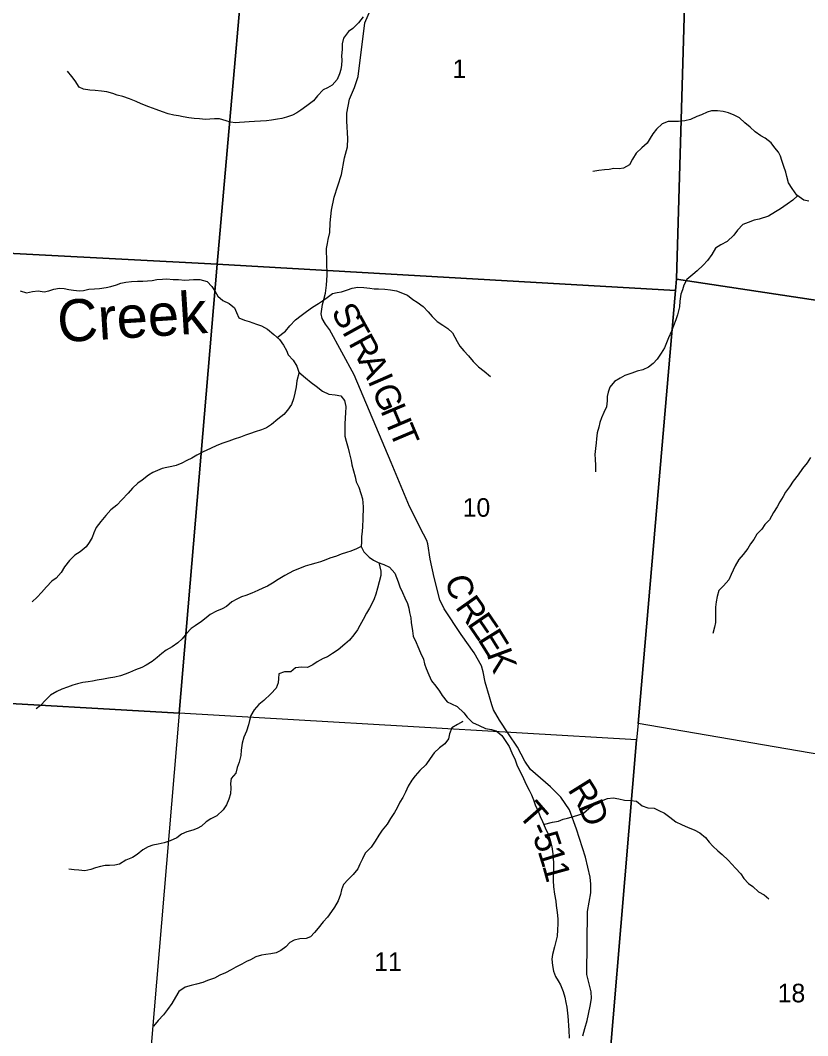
# Model space of a CAD drawing. Extents: x 0 to 34, y 0 to 22.
# Drawn here: x 26.568 to 28.342, y 14.481 to 16.768 of the extents above; entities that cross this region are included whole.
import ezdxf

# ---------------------------------------------------------------- set-up
doc = ezdxf.new("R2010")
doc.units = 0
for name, color, linetype in [('GM_X_Minor_River', 7, 'Continuous'), ('GM_X_Minor_River_Text', 7, 'Continuous'), ('GM_X_Section', 7, 'Continuous'), ('GM_X_Section_Text', 7, 'Continuous'), ('GM_X_Township_Road', 7, 'Continuous'), ('GM_X_Township_Road_Text', 7, 'Continuous')]:
    doc.layers.add(name, color=color, linetype=linetype)

msp = doc.modelspace()

# ---------------------------------------------------------------- linework, layer by layer
at = {"layer": 'GM_X_Minor_River'}
for points in [[(27.3405, 16.7762), (27.33, 16.7628), (27.3176, 16.7497), (27.3077, 16.7431), (27.2964, 16.7285), (27.2935, 16.7153), (27.2933, 16.7028), (27.2922, 16.6884), (27.2924, 16.6785), (27.2919, 16.6675), (27.2901, 16.6573), (27.2877, 16.6475), (27.2818, 16.6347), (27.2709, 16.6224), (27.2606, 16.6161), (27.2507, 16.6114), (27.2379, 16.598), (27.2286, 16.5871), (27.2141, 16.576), (27.2006, 16.5657), (27.191, 16.5598), (27.1815, 16.555), (27.1681, 16.5504), (27.1575, 16.5475), (27.1476, 16.5454), (27.1339, 16.543), (27.1226, 16.5421), (27.1093, 16.5412), (27.096, 16.5403), (27.0835, 16.5398), (27.0737, 16.5389), (27.0623, 16.5379), (27.0528, 16.5374), (27.0419, 16.5387), (27.0317, 16.5415), (27.0171, 16.5464), (27.0057, 16.5466), (26.9955, 16.5456), (26.9856, 16.5451), (26.972, 16.5465), (26.9599, 16.5475), (26.9482, 16.5488), (26.9354, 16.5509), (26.9245, 16.553), (26.9143, 16.5544), (26.9015, 16.5577), (26.8883, 16.5625), (26.874, 16.5677), (26.8575, 16.5733), (26.8402, 16.5804), (26.8293, 16.5852), (26.8143, 16.5915), (26.7989, 16.5964), (26.7868, 16.6), (26.7767, 16.6036), (26.7635, 16.6069), (26.7514, 16.609), (26.7371, 16.6101), (26.725, 16.6111), (26.711, 16.6132), (26.7009, 16.618), (26.692, 16.6318), (26.6847, 16.6414), (26.6747, 16.6537)], [(28.3447, 16.3609), (28.333, 16.363), (28.3173, 16.3747), (28.307, 16.3893), (28.2989, 16.4024), (28.2954, 16.4168), (28.2925, 16.4264), (28.2886, 16.4393), (28.2839, 16.4523), (28.2807, 16.4619), (28.276, 16.4714), (28.2682, 16.4811), (28.2601, 16.4926), (28.2463, 16.5027), (28.2366, 16.5082), (28.2235, 16.5172), (28.2123, 16.5273), (28.2004, 16.5377), (28.1881, 16.549), (28.1761, 16.5549), (28.1633, 16.5597), (28.1513, 16.5626), (28.1385, 16.5647), (28.1256, 16.5642), (28.1157, 16.5617), (28.1031, 16.5551), (28.092, 16.5515), (28.0779, 16.545), (28.0654, 16.5418), (28.0513, 16.5402), (28.0279, 16.5406), (28.0145, 16.5352), (28.0018, 16.5229), (27.9933, 16.5124), (27.9874, 16.5027), (27.9808, 16.4918), (27.9681, 16.4807), (27.9557, 16.4688), (27.9472, 16.4553), (27.9405, 16.4429), (27.9271, 16.4355), (27.9172, 16.4338), (27.9051, 16.4341), (27.8949, 16.4323), (27.8846, 16.4314), (27.8717, 16.4301), (27.8584, 16.4277)], [(28.3193, 16.3732), (28.3084, 16.3631), (28.2961, 16.3542), (28.2808, 16.3439), (28.2696, 16.3365), (28.2539, 16.327), (28.2326, 16.3205), (28.2212, 16.3177), (28.2079, 16.3127), (28.1961, 16.3083), (28.1837, 16.2953), (28.1755, 16.2844), (28.1605, 16.2699), (28.1467, 16.2622), (28.1341, 16.2549), (28.1259, 16.241), (28.1162, 16.2275), (28.1069, 16.2163), (28.093, 16.2041), (28.0834, 16.1959), (28.0696, 16.184), (28.0629, 16.1716), (28.0601, 16.1614), (28.0565, 16.1516), (28.0539, 16.1354), (28.0529, 16.1229), (28.0488, 16.1051), (28.0448, 16.0938), (28.0396, 16.0799), (28.0356, 16.0682), (28.0285, 16.0532), (28.0241, 16.0419), (28.0194, 16.0306), (28.0119, 16.0182), (28.003, 16.0051), (27.9941, 15.9954), (27.9837, 15.9865), (27.9707, 15.9807), (27.9578, 15.9779), (27.946, 15.9732), (27.9304, 15.9678), (27.9193, 15.9623), (27.907, 15.9549), (27.8962, 15.9419), (27.8922, 15.9302), (27.8905, 15.9204), (27.8903, 15.9109), (27.8885, 15.8976), (27.883, 15.8848), (27.8775, 15.8724), (27.8739, 15.8619), (27.8714, 15.8517), (27.8681, 15.8388), (27.866, 15.8256), (27.8654, 15.8161), (27.8637, 15.8033), (27.8623, 15.79), (27.8632, 15.7798), (27.8637, 15.765), (27.8638, 15.7513)], [(26.5681, 16.1592), (26.5823, 16.1544), (26.5956, 16.1572), (26.6089, 16.1588), (26.6221, 16.1567), (26.6328, 16.1591), (26.6442, 16.1627), (26.6563, 16.1648), (26.6669, 16.1642), (26.6775, 16.1621), (26.688, 16.1604), (26.7013, 16.1586), (26.7107, 16.1596), (26.7229, 16.1624), (26.7358, 16.1636), (26.7468, 16.1642), (26.7616, 16.1666), (26.7722, 16.1686), (26.7852, 16.1726), (26.7951, 16.1758), (26.8061, 16.1782), (26.8186, 16.1799), (26.8323, 16.1808), (26.844, 16.1809), (26.8546, 16.1811), (26.8652, 16.1821), (26.8762, 16.1845), (26.8887, 16.1854), (26.8986, 16.1856), (26.9126, 16.1846), (26.9243, 16.184), (26.939, 16.1829), (26.9489, 16.1835), (26.9587, 16.1845), (26.9731, 16.1846), (26.9893, 16.1801), (26.9997, 16.1689), (27.0074, 16.1574), (27.0133, 16.1466), (27.0245, 16.137), (27.0387, 16.1306), (27.0506, 16.1205), (27.055, 16.1102), (27.0604, 16.098), (27.0732, 16.0928), (27.0841, 16.0896), (27.1007, 16.0839), (27.1116, 16.0803), (27.125, 16.0721), (27.1392, 16.0608), (27.1519, 16.0492), (27.1614, 16.0361), (27.1677, 16.0243)], [(27.147, 16.0537), (27.1658, 16.0679), (27.1755, 16.0802), (27.1886, 16.0933), (27.2013, 16.1029), (27.2132, 16.1122), (27.2267, 16.1221), (27.2397, 16.1302), (27.2493, 16.1365), (27.2596, 16.1435), (27.2719, 16.1528), (27.2822, 16.1552), (27.292, 16.1566), (27.305, 16.1609), (27.3157, 16.1648), (27.3286, 16.1669), (27.3418, 16.1663), (27.3554, 16.1645), (27.3656, 16.1635), (27.3754, 16.1637), (27.3894, 16.1623), (27.4026, 16.1613), (27.4155, 16.1592), (27.4402, 16.1488), (27.4522, 16.1395), (27.4623, 16.1336), (27.4757, 16.1239), (27.4872, 16.1112), (27.4961, 16.1011), (27.5076, 16.0899), (27.5203, 16.0813), (27.5316, 16.0743), (27.542, 16.0642), (27.5471, 16.0543), (27.5526, 16.0447), (27.5584, 16.034), (27.5673, 16.0239), (27.5781, 16.0124), (27.5884, 15.9996), (27.6007, 15.9873), (27.6134, 15.9775), (27.6275, 15.9659)], [(27.1677, 16.0243), (27.1716, 16.0143), (27.1828, 16.0027), (27.1916, 15.9893), (27.1959, 15.9759), (27.2108, 15.9628), (27.2238, 15.9526), (27.2346, 15.9437), (27.2492, 15.9324), (27.2631, 15.9261), (27.2774, 15.9247), (27.2902, 15.9222), (27.2987, 15.9114), (27.3015, 15.8981), (27.3009, 15.8833), (27.3003, 15.8731), (27.2992, 15.8575), (27.2993, 15.8431), (27.2995, 15.831), (27.3023, 15.8203), (27.3069, 15.8043), (27.309, 15.7948), (27.3136, 15.7765), (27.3153, 15.767), (27.3188, 15.7529), (27.3227, 15.7395), (27.3252, 15.7285), (27.3306, 15.7166), (27.3357, 15.7025), (27.3388, 15.6903), (27.3404, 15.672), (27.3399, 15.644), (27.3392, 15.6277), (27.3382, 15.6167), (27.3372, 15.605), (27.3366, 15.5928), (27.3364, 15.5826), (27.3423, 15.5711), (27.3541, 15.5587), (27.3639, 15.5517), (27.3747, 15.547), (27.3871, 15.5422), (27.4003, 15.5359), (27.4121, 15.5224), (27.4193, 15.5033), (27.4233, 15.4918), (27.4291, 15.4788), (27.4349, 15.4673), (27.4404, 15.4547), (27.4436, 15.444), (27.4453, 15.4341), (27.4477, 15.4223), (27.449, 15.4117), (27.4521, 15.3927), (27.4533, 15.3805), (27.4603, 15.3667), (27.4639, 15.3572), (27.4697, 15.343), (27.4766, 15.3288), (27.479, 15.3186), (27.4826, 15.3082), (27.4888, 15.2933), (27.4946, 15.2803), (27.5042, 15.268), (27.5127, 15.2565), (27.5186, 15.2469), (27.53, 15.233), (27.5398, 15.2279), (27.5525, 15.222), (27.5678, 15.208), (27.5752, 15.1984), (27.5867, 15.1864), (27.6021, 15.1793), (27.6159, 15.173), (27.6299, 15.1701), (27.6404, 15.1672), (27.6531, 15.1567), (27.6609, 15.146), (27.6693, 15.1318), (27.6758, 15.118), (27.6827, 15.1019), (27.6874, 15.0889), (27.6962, 15.0728), (27.702, 15.0598), (27.7082, 15.0468), (27.7144, 15.0334), (27.7198, 15.0235), (27.7242, 15.0116), (27.7285, 15.0009), (27.735, 14.9864), (27.7397, 14.9742), (27.7444, 14.9631), (27.7506, 14.9485), (27.7571, 14.9344), (27.7618, 14.921), (27.7657, 14.9058), (27.768, 14.8902), (27.7696, 14.87), (27.7697, 14.856), (27.769, 14.8431), (27.7688, 14.8302)], [(27.1962, 15.9756), (27.191, 15.9563), (27.1899, 15.9423), (27.1867, 15.9283), (27.1838, 15.9158), (27.179, 15.903), (27.1704, 15.8899), (27.1619, 15.8802), (27.1481, 15.8695), (27.1342, 15.858), (27.1231, 15.8502), (27.1113, 15.8459), (27.0976, 15.8409), (27.0869, 15.8373), (27.0759, 15.8333), (27.064, 15.829), (27.0503, 15.8243), (27.0381, 15.8204), (27.0244, 15.8153), (27.0111, 15.8106), (26.9966, 15.8037), (26.9802, 15.7964), (26.9656, 15.7883), (26.9549, 15.7821), (26.9434, 15.7762), (26.9324, 15.7708), (26.9194, 15.7649), (26.9095, 15.7632), (26.8981, 15.7604), (26.8879, 15.7583), (26.8775, 15.754), (26.8669, 15.7492), (26.8569, 15.7434), (26.8427, 15.7322), (26.8327, 15.7256), (26.8212, 15.7141), (26.8111, 15.7033), (26.7968, 15.6876), (26.7856, 15.676), (26.7725, 15.6653), (26.761, 15.6526), (26.7497, 15.6392), (26.7389, 15.6253), (26.7341, 15.6137), (26.7301, 15.6027), (26.7231, 15.5915), (26.7165, 15.5818), (26.703, 15.571), (26.6908, 15.5629), (26.6792, 15.551), (26.6679, 15.5368), (26.6605, 15.524), (26.6493, 15.5113), (26.6397, 15.5047), (26.6273, 15.492), (26.6157, 15.479), (26.6065, 15.4689), (26.5953, 15.4581)], [(28.3485, 15.7835), (28.3407, 15.7712), (28.3306, 15.7588), (28.3205, 15.7442), (28.3093, 15.73), (28.3011, 15.7173), (28.2921, 15.7053), (28.2867, 15.6955), (28.2792, 15.6836), (28.273, 15.6723), (28.2648, 15.6595), (28.2558, 15.643), (28.2457, 15.6326), (28.2391, 15.6221), (28.2275, 15.6109), (28.2209, 15.5985), (28.2131, 15.5888), (28.2072, 15.5783), (28.1967, 15.5645), (28.1871, 15.5537), (28.1789, 15.5394), (28.1738, 15.5296), (28.1694, 15.5199), (28.1643, 15.5078), (28.1527, 15.4944), (28.1422, 15.4836), (28.1382, 15.4704), (28.1361, 15.4579), (28.1343, 15.4458), (28.1341, 15.4356), (28.1346, 15.4223), (28.1341, 15.4113), (28.1323, 15.4007), (28.1287, 15.3871)], [(27.3364, 15.5826), (27.3254, 15.5775), (27.3128, 15.572), (27.3032, 15.5692), (27.2914, 15.5652), (27.2804, 15.5613), (27.2659, 15.5562), (27.2564, 15.5526), (27.2449, 15.5479), (27.2343, 15.5451), (27.2206, 15.5415), (27.2103, 15.5383), (27.1974, 15.5332), (27.1836, 15.5278), (27.1741, 15.5227), (27.1641, 15.5172), (27.1492, 15.5087), (27.1362, 15.5003), (27.1254, 15.4933), (27.1148, 15.4889), (27.1033, 15.4838), (27.0899, 15.4776), (27.0766, 15.4726), (27.0663, 15.469), (27.056, 15.4642), (27.0449, 15.458), (27.0326, 15.4472), (27.0227, 15.4421), (27.0101, 15.4374), (26.9963, 15.4297), (26.9867, 15.4219), (26.9767, 15.4137), (26.9625, 15.4042), (26.9529, 15.3979), (26.9425, 15.3867), (26.9328, 15.3744), (26.9228, 15.3658), (26.9101, 15.3566), (26.8971, 15.3489), (26.8868, 15.3419), (26.8768, 15.3326), (26.8656, 15.324), (26.8522, 15.3156), (26.8423, 15.3101), (26.8278, 15.305), (26.8144, 15.2985), (26.8045, 15.2949), (26.7939, 15.2916), (26.7809, 15.2881), (26.7673, 15.2861), (26.7555, 15.2836), (26.7414, 15.2816), (26.7308, 15.2796), (26.7213, 15.2782), (26.7095, 15.2762), (26.697, 15.273), (26.6864, 15.2705), (26.6745, 15.2658), (26.662, 15.2611), (26.6509, 15.2564), (26.6367, 15.2479), (26.6256, 15.2375), (26.614, 15.2245), (26.6043, 15.2167)], [(27.376, 15.5465), (27.3808, 15.5271), (27.3806, 15.5173), (27.3766, 15.5033), (27.3729, 15.489), (27.3692, 15.475), (27.3652, 15.4648), (27.3601, 15.4536), (27.355, 15.4438), (27.3484, 15.4325), (27.3409, 15.4186), (27.3331, 15.4048), (27.328, 15.395), (27.3198, 15.3838), (27.3097, 15.3718), (27.2997, 15.3625), (27.2847, 15.3503), (27.2713, 15.3414), (27.2606, 15.3344), (27.2503, 15.3301), (27.2373, 15.3227), (27.2273, 15.3161), (27.2155, 15.3102), (27.2018, 15.3105), (27.1882, 15.3092), (27.1774, 15.3003), (27.1638, 15.3002), (27.1509, 15.2959), (27.1499, 15.2853), (27.1493, 15.2758), (27.1449, 15.2634), (27.1326, 15.2507), (27.1172, 15.2355), (27.1056, 15.2266), (27.0952, 15.2147), (27.0878, 15.2019), (27.0845, 15.191), (27.0821, 15.1808), (27.078, 15.1668), (27.0721, 15.1533), (27.0684, 15.1397), (27.0658, 15.1238), (27.0652, 15.1117), (27.0612, 15.0966), (27.0572, 15.0849), (27.0535, 15.0724), (27.0434, 15.0601), (27.0417, 15.0491), (27.0427, 15.0393), (27.0417, 15.0256), (27.0384, 15.0136), (27.0329, 15.0008), (27.0251, 14.9891), (27.0112, 14.9761), (26.9974, 14.9688), (26.9867, 14.9622), (26.9763, 14.9529), (26.9667, 14.9474), (26.9568, 14.9434), (26.9432, 14.9402), (26.9313, 14.9344), (26.9206, 14.9266), (26.906, 14.9197), (26.8923, 14.9154), (26.879, 14.9122), (26.8665, 14.9098), (26.8562, 14.9058), (26.8447, 14.8992), (26.8313, 14.8885), (26.8213, 14.8822), (26.8064, 14.8757), (26.7919, 14.8672), (26.7812, 14.8644), (26.7695, 14.8642), (26.7593, 14.8641), (26.749, 14.862), (26.7376, 14.8588), (26.7273, 14.8548), (26.7136, 14.852), (26.7, 14.8538), (26.6898, 14.8544), (26.6778, 14.8561)], [(27.5644, 15.1876), (27.5651, 15.1883), (27.5529, 15.1818), (27.5407, 15.1744), (27.5355, 15.1608), (27.5326, 15.1495), (27.5244, 15.1379), (27.5126, 15.1294), (27.5006, 15.1175), (27.4917, 15.1051), (27.4815, 15.0909), (27.4681, 15.0779), (27.458, 15.066), (27.4506, 15.0559), (27.4424, 15.0431), (27.4357, 15.0296), (27.4298, 15.0172), (27.4236, 15.0067), (27.4169, 14.9939), (27.411, 14.9834), (27.402, 14.9699), (27.3946, 14.9571), (27.3838, 14.9433), (27.3756, 14.9321), (27.3678, 14.9186), (27.3584, 14.9055), (27.3449, 14.8921), (27.339, 14.8793), (27.3331, 14.8669), (27.3284, 14.8567), (27.3179, 14.844), (27.3071, 14.8321), (27.2963, 14.8209), (27.2919, 14.8089), (27.2894, 14.7987), (27.2846, 14.7847), (27.276, 14.7701), (27.2694, 14.76), (27.2604, 14.7473), (27.2508, 14.7368), (27.2396, 14.723), (27.2314, 14.7133), (27.2218, 14.7029), (27.2119, 14.6993), (27.1982, 14.6984), (27.1849, 14.696), (27.1754, 14.6905), (27.1668, 14.6808), (27.1549, 14.6723), (27.145, 14.6675), (27.1329, 14.6647), (27.1215, 14.6634), (27.1116, 14.6617), (27.099, 14.6581), (27.0872, 14.6512), (27.0776, 14.6475), (27.0673, 14.642), (27.054, 14.6351), (27.0436, 14.6292), (27.0302, 14.6223), (27.0177, 14.6172), (27.0054, 14.6102), (26.9902, 14.6048), (26.9795, 14.6005), (26.9654, 14.5969), (26.9532, 14.5937), (26.9396, 14.5898), (26.9257, 14.5799), (26.9179, 14.5671), (26.9097, 14.5528), (26.8996, 14.5398), (26.8911, 14.5274), (26.8791, 14.5147), (26.8686, 14.5017)], [(27.7472, 14.9565), (27.7671, 14.9615), (27.7804, 14.9639), (27.7911, 14.9683), (27.8006, 14.9707), (27.8143, 14.9743), (27.8265, 14.9782), (27.8368, 14.9822), (27.8491, 14.9922), (27.8621, 15.0014), (27.8812, 15.0109), (27.8908, 15.0149), (27.9037, 15.0166), (27.9169, 15.0141), (27.9297, 15.0115), (27.9437, 15.0101), (27.9561, 15.0088), (27.9688, 14.9987), (27.9823, 14.9942), (27.9959, 14.9929), (28.0064, 14.9881), (28.0192, 14.9822), (28.0315, 14.9732), (28.0449, 14.9623), (28.0577, 14.956), (28.0731, 14.9497), (28.0862, 14.9445), (28.0994, 14.9374), (28.1116, 14.9273), (28.1198, 14.9169), (28.1283, 14.9073), (28.1398, 14.8972), (28.1495, 14.8887), (28.1629, 14.8763), (28.1792, 14.8582), (28.1915, 14.845), (28.1985, 14.835), (28.2088, 14.8235), (28.2186, 14.8164), (28.2316, 14.8048), (28.2443, 14.7978), (28.2548, 14.7892)], [(27.7688, 14.8302), (27.7693, 14.8158), (27.772, 14.7991), (27.7747, 14.7835), (27.7757, 14.7736), (27.7777, 14.7584), (27.7789, 14.7439), (27.7791, 14.7329), (27.7788, 14.7189), (27.7774, 14.7049), (27.7749, 14.6928), (27.772, 14.6811), (27.7668, 14.6634), (27.7655, 14.6532), (27.7671, 14.6387), (27.7695, 14.6258), (27.7738, 14.6139), (27.7797, 14.6043), (27.7852, 14.5948), (27.7913, 14.5802), (27.7952, 14.5676), (27.7973, 14.5555), (27.7994, 14.5448), (27.802, 14.5246), (27.8026, 14.5144), (27.8031, 14.5026), (27.8037, 14.4928), (27.8049, 14.4749)]]:
    msp.add_lwpolyline(points, dxfattribs=at)
at = {"layer": 'GM_X_Section'}
for points in [[(26.2538, 17.2713), (27.0604, 17.2208), (27.0998, 17.2184), (27.0114, 16.2186), (25.9802, 16.2732), (26.0152, 16.9679), (26.1318, 17.0242)], [(27.0998, 17.2184), (28.0732, 17.1088), (28.0465, 16.1852), (28.0441, 16.1595), (27.0114, 16.2186)], [(28.0732, 17.1088), (28.8721, 17.0617), (28.8121, 16.0697), (28.0465, 16.1852)], [(27.0114, 16.2186), (26.9263, 15.2069), (25.9296, 15.2643), (25.9802, 16.2732)], [(28.0441, 16.1595), (27.9603, 15.1837), (27.9567, 15.147), (26.9263, 15.2069), (27.0114, 16.2186)], [(28.0441, 16.1595), (28.0465, 16.1852), (28.8121, 16.0697), (28.7351, 15.051), (27.9603, 15.1837)], [(26.9263, 15.2069), (26.8411, 14.2004), (25.8818, 14.3145), (25.9296, 15.2643)]]:
    msp.add_lwpolyline(points, close=True, dxfattribs=at)
for points in [[(27.8688, 14.1), (27.9567, 15.147), (26.9263, 15.2069), (26.8411, 14.2004), (27.694, 14.1)], [(28.67, 14.1), (28.7351, 15.051), (27.9603, 15.1837), (27.9567, 15.147), (27.8688, 14.1)]]:
    msp.add_lwpolyline(points, dxfattribs=at)
at = {"layer": 'GM_X_Township_Road'}
for points in [[(27.6326, 15.2196), (27.6303, 15.2263), (27.6249, 15.2444), (27.6157, 15.2774), (27.611, 15.3005), (27.6071, 15.3139), (27.5908, 15.3435), (27.5615, 15.3847), (27.5233, 15.442), (27.5137, 15.4623), (27.5007, 15.513), (27.4919, 15.5545), (27.4867, 15.5889), (27.4841, 15.5963), (27.4763, 15.6103), (27.4453, 15.6732), (27.4041, 15.7724), (27.3204, 15.9696), (27.2648, 16.0715), (27.2559, 16.0835), (27.2483, 16.0964), (27.2463, 16.107), (27.249, 16.1282), (27.2561, 16.1532), (27.2577, 16.1713), (27.2593, 16.1938), (27.2584, 16.2541), (27.2604, 16.2654), (27.2621, 16.2743), (27.2657, 16.2902), (27.2663, 16.312), (27.2693, 16.3409), (27.2756, 16.3697), (27.2915, 16.4211), (27.2984, 16.4582), (27.3053, 16.483), (27.3062, 16.5017), (27.3038, 16.5411), (27.3035, 16.5591), (27.3098, 16.5908), (27.3215, 16.6172), (27.3291, 16.642), (27.3446, 16.7624), (27.3572, 16.7917)], [(27.8354, 14.4804), (27.8399, 14.4965), (27.8453, 14.5148), (27.8524, 14.547), (27.8551, 14.5645), (27.8542, 14.5797), (27.8448, 14.6182), (27.8457, 14.7602), (27.8536, 14.8027), (27.8539, 14.822), (27.8521, 14.8377), (27.8414, 14.8826), (27.8211, 14.9458), (27.8054, 14.9893), (27.7858, 15.0176), (27.7629, 15.0411), (27.7177, 15.08), (27.7046, 15.0988), (27.6883, 15.1303), (27.6681, 15.1607), (27.6475, 15.1918), (27.6342, 15.2147), (27.6326, 15.2196)]]:
    msp.add_lwpolyline(points, dxfattribs=at)

# ---------------------------------------------------------------- texts
at = {"layer": 'GM_X_Minor_River_Text'}
msp.add_text('Creek', height=0.09469, rotation=3.6301, dxfattribs=at).set_placement((26.6545, 16.0425))
at = {"layer": 'GM_X_Section_Text'}
for s, height, p in [('1', 0.0419, (27.5418, 16.6381)), ('10', 0.04186, (27.5647, 15.6498)), ('11', 0.04186, (27.3655, 14.6265)), ('18', 0.04186, (28.2743, 14.5557))]:
    msp.add_text(s, height=height, rotation=0, dxfattribs=at).set_placement(p)
at = {"layer": 'GM_X_Township_Road_Text'}
for s, rotation, p in [('S', 298.9988, (27.2674, 16.1119)), ('T', 298.9922, (27.2859, 16.0783)), ('R', 298.6111, (27.3065, 16.0412)), ('A', 295.9232, (27.3285, 16.0009)), ('I', 293.5963, (27.3501, 15.9565)), ('G', 292.9542, (27.3594, 15.9353)), ('H', 292.9298, (27.3789, 15.8892)), ('T', 292.9321, (27.3984, 15.8432)), ('C', 285.39, (27.5248, 15.5107)), ('R', 305.4716, (27.5465, 15.4461)), ('E', 304.4057, (27.5734, 15.4084)), ('E', 301.9354, (27.5971, 15.3738)), ('K', 290.3049, (27.6182, 15.3405)), ('R', 302.0401, (27.8002, 15.035)), ('T', 311.1424, (27.6876, 14.9775)), ('D', 292.2046, (27.8238, 14.9978)), ('5', 288.723, (27.7223, 14.9293)), ('-', 294.5363, (27.7132, 14.9491)), ('1', 287.3537, (27.7335, 14.8965)), ('1', 285.2935, (27.7438, 14.8636))]:
    msp.add_text(s, height=0.0568, rotation=rotation, dxfattribs=at).set_placement(p)

doc.saveas('drawing.dxf')
